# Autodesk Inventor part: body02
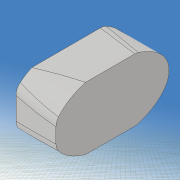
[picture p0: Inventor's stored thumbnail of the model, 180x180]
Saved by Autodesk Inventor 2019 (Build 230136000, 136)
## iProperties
Created: 2020-12
Part Number: body02
Material: 一般
Document SubType Name: Modeling
Designer: kikut
Density: 1 g/cm^3
Appearance: 既定
Mass: 87.6477 g
Surface Area: 156.124 cm^2
Volume: 87.6477 cm^3
Author: kikut
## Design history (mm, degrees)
sketch "スケッチ1"
  geometry: L1 (-100, -20)-(100, -20); L2 (100, -20)-(100, 20); L3 (100, 20)-(-100, 20); L4 (-100, 20)-(-100, -20); L5 (-100, -20)-(100, 20); L6 (100, -20)-(-100, 20); 1 further point
  constraints: 12 end point, 2 midpoint, 2 parallel, 1 horizontal, 1 perpendicular
  dimensions: "d0" = 40 distance of L3.end L1.start; "d1" = 200 distance of L2.end L3.end
extrude "押し出し1" new body sketch "スケッチ1" stored distance "d2" = 60; taper "d3" = 0 deg
sketch "スケッチ2"
  geometry: L1 (0, -60)-(0, 0) reference; L2 (200, -60)-(200, 0) reference; L3 (0, 0)-(200, 0) reference; L4 (200, -60)-(0, -60) reference; L5 (0, -26)-(0, -32); L6 (194, -10)-(194, -13); L7 (194, -13)-(174, -33); L8 (174, -33)-(200, -58); L9 (-20, 20)-(220, 20); L10 (220, 20)-(220, -100); L11 (220, -100)-(-20, -100); L12 (-20, -100)-(-20, 20); 12 further points
  constraints: 16 end point, 4 point on line, 2 parallel, 2 vertical, 1 horizontal, 1 perpendicular, 14 other
  dimensions: "d4" = 32 distance from line of point (32, -12) L1; "d5" = 50 horizontal distance of point (32, -12) point (82, -11); "d6" = 50 horizontal distance of point (132, -17) point (82, -11); "d7" = 12 distance from line of point (32, -12) L3; "d8" = 11 distance from line of point (82, -11) L3; "d10" = 17 distance from line of point (132, -17) L3; "d11" = 26 distance from line of L5.start L3; "d12" = 0 distance from line of point (200, -60) L4; "d13" = 28 distance from line of L5.end L4; "d14" = 12 distance from line of point (28, -48) L4; "d15" = 10 distance from line of point (80, -50) L4; "d16" = 16 distance from line of point (130, -44) L4; "d17" = 28 distance from line of point (28, -48) L1; "d19" = 50 horizontal distance of point (130, -44) point (80, -50); "d20" = 80 distance from line of point (80, -50) L1; "d21" = 6 distance from line of L6.start L2; "d22" = 36 distance from line of point (164, -24) L2; "d23" = 24 distance from line of point (176, -20) L2; "d24" = 10 distance from line of L6.start L3; "d25" = 20 distance from line of point (176, -20) L3; "d26" = 24 distance from line of point (164, -24) L3; "d27" = 40 distance from line of point (160, -40) L2; "d28" = 25 distance from line of point (175, -47.5) L2; "d29" = 12.5 distance from line of point (175, -47.5) L4; "d30" = 20 distance from line of L4 point (160, -40); "d31" = 3 distance of L6.start L6.end; "d32" = 33 distance from line of L7.end L3; "d33" = 26 distance from line of L7.end L2; "d34" = 2 distance of L8.end L2.start; "d35" = 120 distance of L11.end L9.start; "d36" = 240 distance of L10.end L11.end; "d37" = 20 distance between parallel lines of L1 L12; "d38" = 20 distance between parallel lines of L3 L9
extrude "押し出し2" cut sketch "スケッチ2" extent not by distance; stored distance "d39" = 0.02; taper "d40" = 0 deg
sketch "スケッチ8"
  geometry: L1 (-100, -20)-(-100, 20) reference; L2 (100, 20)-(100, -20) reference; L3 (-142.805, 0)-(142.831, 0) reference; L4 (110, 30)-(-110, 30); L5 (-110, 30)-(-110, -30); L6 (-110, -30)-(110, -30); L7 (110, -30)-(110, 30); L8 (110, 30)-(-110, -30); L9 (-110, 30)-(110, -30); L10 (-100, -2)-(-100, 2); L11 (100, -3)-(100, 3); 7 further points
  constraints: 16 end point, 4 point on line, 2 midpoint, 2 parallel, 2 perpendicular, 1 collinear, 1 horizontal, 10 other
  dimensions: "d93" = 2 vertical distance of point (0, 0) L10.end; "d94" = 2 vertical distance of L10.start point (0, 0); "d95" = 35 distance from line of point (-65, -10) L1; "d96" = 0 horizontal distance of point (-65, 10) point (-65, -10); "d97" = 10 vertical distance of point (0, 0) point (-65, -10); "d98" = 10 vertical distance of point (-65, 10) point (0, 0); "d99" = 100 distance from line of point (0, -10) L1; "d100" = 0 horizontal distance of point (0, 10) point (0, -10); "d101" = 10 distance of point (0, -10) point (0, 0); "d102" = 10 distance of point (0, 0) point (0, 10); "d103" = 160 distance from line of point (60, -4) L1; "d104" = 0 horizontal distance of point (60, 4) point (60, -4); "d105" = 4 distance from line of L3 point (60, -4); "d106" = 4 distance from line of L3 point (60, 4); "d107" = 3 distance from line of L11.start L3; "d108" = 3 distance from line of L11.end L3; "d109" = 220 distance of L5.end L6.end; "d110" = 60 distance of L4.end L5.end
extrude "押し出し6" cut sketch "スケッチ8" extent not by distance; stored distance "d111" = 10; taper "d112" = 0 deg
sketch "スケッチ9" dims "d113" = 20, "d114" = 12
  geometry: L1 (-29, -18)-(21, -18); L2 (21, -18)-(21, 22); L3 (21, 22)-(-29, 22); L4 (-29, 22)-(-29, -18); L5 (-29, -18)-(21, 22); L6 (21, -18)-(-29, 22); 2 further points; 1 other entity
  constraints: 12 end point, 2 midpoint, 2 parallel, 1 coincident, 1 horizontal, 1 perpendicular, 2 other
  dimensions: "d115" = 50 distance of L2.end L3.end; "d116" = 40 distance of L1.end L2.end
extrude "押し出し7" cut sketch "スケッチ9" distance "d117" = 150; taper "d118" = 0 deg
fillet "フィレット4" dims "d119" = 4
fillet "フィレット5" dims "d120" = 4
fillet "フィレット6" dims "d121" = 2
node "作業平面2"
sketch "スケッチ10"
  geometry: L1 (0, -41.439)-(0, 38.458) reference; L2 (141.833, 0)-(-140.631, 0) reference; L3 (82.55, 12.983)-(81.45, -4.983); A1 r 9 centre (82, 4) between (82.55, 12.983) and (81.45, -4.983); 1 further point
  constraints: 2 end point, 2 point on circle, 1 centre point
  dimensions: "d123" = 82 distance from line of L1 A1.centre; "d124" = 4 distance from line of L2 A1.centre; "d125" = 9 radius of A1; "d126" = 180 deg dimension on A1.centre L3.end L3.start; "d127" = 90 deg dimension on L3.end point (0, 0) A1.centre
revolve "回転1" sketch "スケッチ10" stored, may be unused: angle "d128" = 90 deg
mirror "ミラー1"
sketch "スケッチ11"
  geometry: L1 (70, 30)-(55, 30); L2 (55, 30)-(55, -30); L3 (55, -30)-(70, -30); L4 (70, -30)-(70, 30); L5 (0, -40.648)-(0, 34.486) reference; L6 (140.69, 0)-(-139.196, 0) reference; L7 (120, 53.792)-(-120, 53.792); L8 (-120, 53.792)-(-120, -46.208); L9 (-120, -46.208)-(120, -46.208); L10 (120, -46.208)-(120, 53.792); 1 further point
  constraints: 16 end point, 4 parallel, 2 horizontal, 2 perpendicular, 2 other
  dimensions: "d129" = 55 distance between parallel lines of L5 L2; "d130" = 15 distance of L1.start L1.end; "d131" = 60 distance of L3.end L1.start; "d132" = 100 distance of L9.end L7.start; "d133" = 240 distance of L7.start L7.end
extrude "押し出し8" cut sketch "スケッチ11" stored distance "d134" = 40; taper "d135" = 0 deg
node "ソリッド1"
other parameters: "d122" = -1
